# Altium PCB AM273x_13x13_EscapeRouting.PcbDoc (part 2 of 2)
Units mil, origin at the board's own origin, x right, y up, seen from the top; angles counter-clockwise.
Board outline 4950 x 3450 mil, 4 copper layers (Top Layer, GND, Power, Bottom Layer), stack 65.634 mil thick; 41 components, 133 nets, 293 pads, 159 vias.
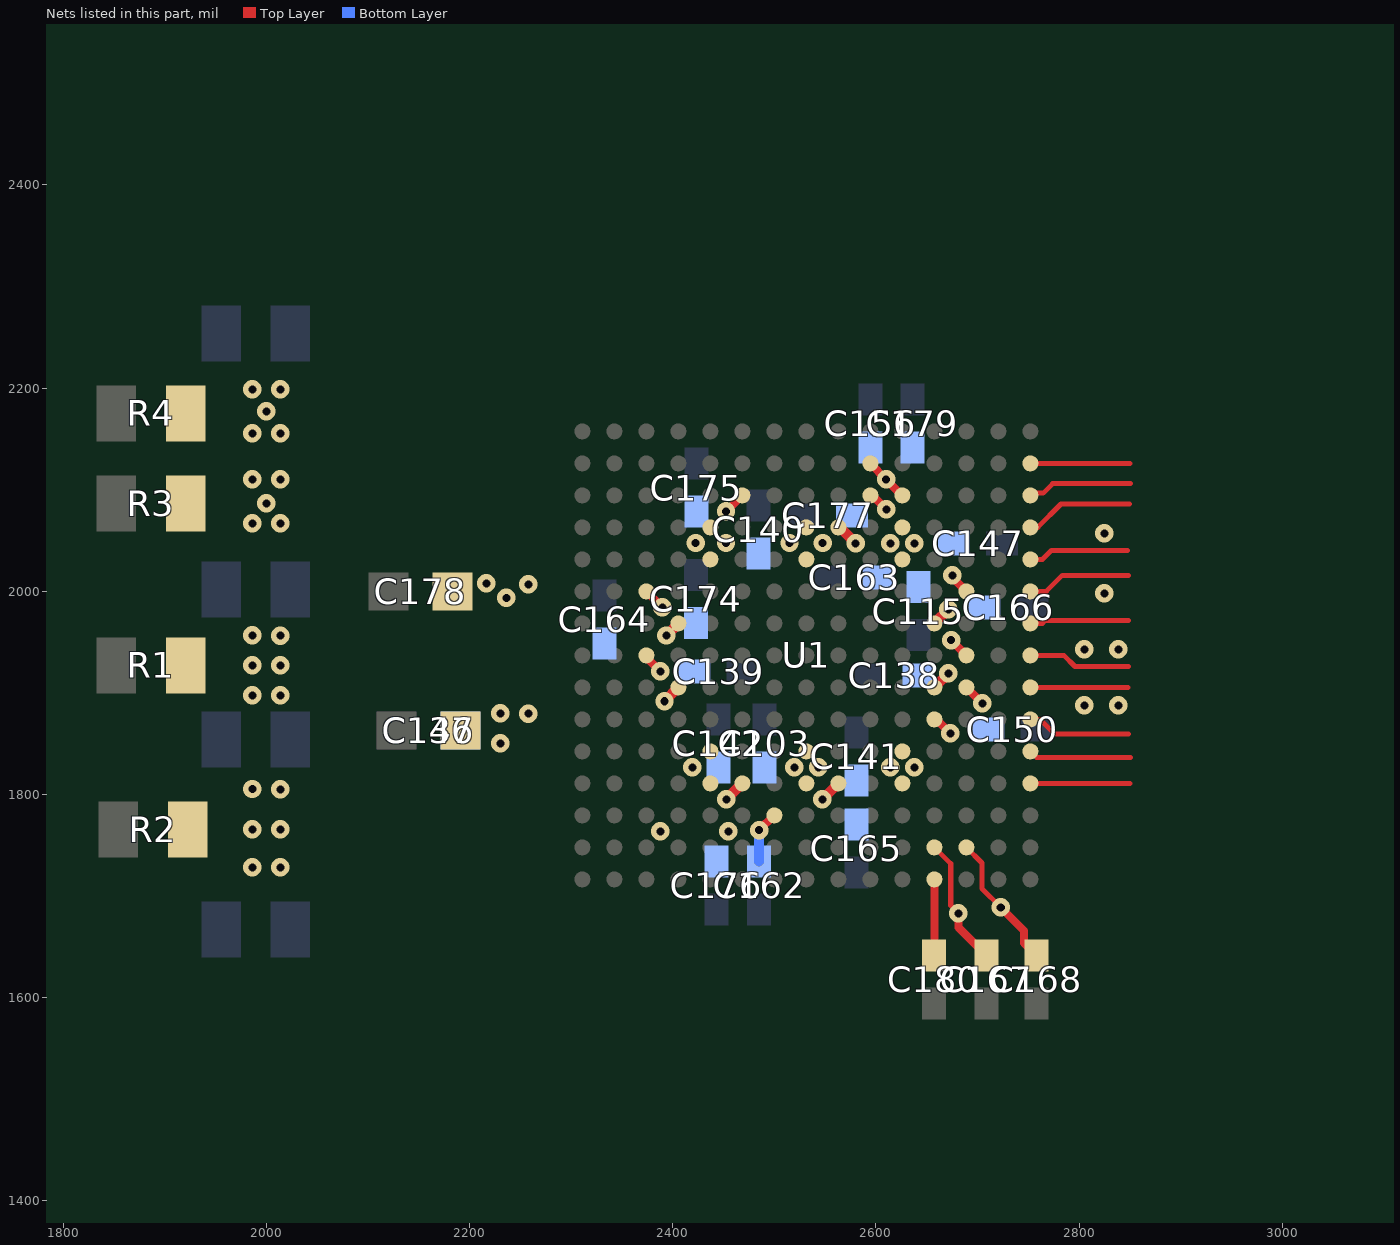
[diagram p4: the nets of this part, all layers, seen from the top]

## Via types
v1: diameter 18, hole 8, Top Layer to Bottom Layer, tented both sides, 135 vias
v2: diameter 18, hole 8, Top Layer to Bottom Layer, 24 vias

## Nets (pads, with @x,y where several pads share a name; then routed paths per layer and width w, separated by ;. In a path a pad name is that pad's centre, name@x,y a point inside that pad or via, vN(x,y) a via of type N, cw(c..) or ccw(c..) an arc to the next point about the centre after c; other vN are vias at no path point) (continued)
R4: U1.R4 | length 98
  Top Layer w5: U1.R4@2751.97,1811.02 2850,1811.02
R5: U1.R5 | length 100.9
  Top Layer w5: U1.R5@2751.97,1842.52 2757.87,1836.61 2850.39,1836.61
R6: U1.R6 | length 102.4
  Top Layer w5: U1.R6@2751.97,1874.02 2761.53,1874.02 2775.87,1859.68 2848.42,1859.68
R7: U1.R7 | length 96.2
  Top Layer w5: U1.R7@2751.97,1905.51 2848.18,1905.51
R8: U1.R8 | length 101
  Top Layer w5: U1.R8@2751.97,1937.01 2784.92,1937.01 2795.97,1925.95 2848.43,1925.95
R9: U1.R9 | length 97.6
  Top Layer w5: U1.R9@2751.97,1968.5 2763.78,1968.5 2766.59,1971.32 2848.43,1971.32
R10: U1.R10 | length 103
  Top Layer w5: U1.R10@2751.97,2000 2767.72,2000 2783.46,2015.75 2848.43,2015.75
R11: U1.R11 | length 99.1
  Top Layer w5: U1.R11@2751.97,2031.5 2763.9,2031.5 2772.76,2040.35 2847.44,2040.35
R12: U1.R12 | length 107.2
  Top Layer w5: U1.R12@2751.97,2062.99 2759.21,2062.99 2782.21,2085.98 2849.68,2085.98
R13: U1.R13 | length 104.4
  Top Layer w5: U1.R13@2751.97,2094.49 2751.97,2096.61 2764.55,2096.61 2773.92,2105.98 2850.39,2105.98
R14: U1.R14 | length 98
  Top Layer w5: U1.R14@2751.97,2125.98 2850,2125.98
VBGAP: C180.2 U1.M1 | length 75
  Top Layer w8: C180.2@2656.89,1641.73 2657.48,1642.32 U1.M1@2657.48,1716.54
VDD_1V2: C103.2 C115.2 C137.2 C138.2 C139.2 C140.2 C141.2 C142.2 C146.2 C156.2 C162.2 C179.2 R1.2 U1.D7 U1.D9 U1.E4 U1.E5 U1.E11 U1.E12 U1.G3 U1.H4 U1.H5 U1.H11 U1.H12 U1.K14 U1.L4 U1.L5 U1.L11 U1.L12 U1.L13 U1.M6 U1.M7 U1.M9 | length 196.6
  Top Layer w8: v1(2485,1765) 2499.53,1779.53 U1.G3@2500,1779.53 ; U1.K14@2594.49,2125.98 2594.49,2125.75 v1(2610,2110.24) 2625.75,2094.49 U1.L13@2625.98,2094.49 ; U1.M6@2657.48,1874.02 2659.45,1874.02 v1(2673.23,1860.24)
  Top Layer w10: v1(2391.87,1891.87) U1.D7@2405.51,1905.51 ; v1(2393.7,1956.46) 2405.51,1968.27 U1.D9@2405.51,1968.5 ; U1.M7@2657.48,1905.51 v1@2672.5,1920.49 ; U1.M9@2657.48,1968.5 v1@2672.5,1983.48
  Bottom Layer w10: C162.2@2485,1734.25 v1(2485,1765)
  other v1: 2419.29,1826.77 2519.68,1826.77 2543.31,1826.77 2614.17,1826.77 2637.8,1826.77 2230.32,1850.39 2230.32,1879.92 2257.87,1879.66 2671.26,1919.29 2671.26,1982.28 2614.17,2047.24 2637.8,2047.24 2422.5,2047.5 2452.5,2047.5 2515,2047.5 2547.5,2047.5
  other v2: 1986.22,1897.64 2013.78,1897.64 1986.22,1927.17 2013.78,1927.17 2013.78,1956.38 1986.22,1956.69
VDD_1V8: C163.2 C164.2 C165.2 C166.2 C167.2 C168.2 R2.2 U1.C8 U1.J4 U1.J12 U1.M2 U1.N2 U1.N8 | length 351.5
  Top Layer w5: U1.M2@2657.48,1748.03 2673.6,1731.91 2673.6,1690.96 2681.49,1683.07 v1(2681.1,1683.07) ; U1.N2@2688.98,1748.03 2704.39,1732.62 2704.39,1707.38 v1(2722.8,1688.98)
  Top Layer w8: U1.C8@2374.02,1937.01 2374.02,1935.04 v1(2387.8,1921.26) ; v1(2674,1951.99) U1.N8@2688.98,1937.01 ; v1(2681.1,1683.07) 2681.1,1669.29 C167.2@2708.66,1641.73 ; v1(2722.8,1688.98) 2745.86,1665.91 2745.86,1653.74 C168.2@2757.87,1641.73
  Top Layer w10: v1(2547.24,1795.27) 2547.35,1795.27 2563.1,1811.02 U1.J4@2562.99,1811.02 ; U1.J12@2562.99,2062.99 2564.25,2062.99 v1(2580,2047.24)
  other v1: 2387.8,1763.78 2454.72,1763.78 2805.12,1887.8 2838.58,1887.8 2805.12,1942.91 2838.58,1942.91
  other v2: 1986.22,1728.35 2013.78,1728.35 1986.22,1765.75 2013.78,1765.75 1986.22,1805.37 2013.78,1805.12
VDD_3V3: C147.2 C174.2 C175.2 C176.2 C177.2 C178.2 R3.2 U1.C10 U1.F4 U1.F13 U1.K13 U1.N10 | length 111.8
  Top Layer w8: U1.C10@2374.02,2000 2384.35,1989.66 v1@2389.76,1984.26 ; v1(2452.5,2078.74) 2468.25,2094.49 U1.F13@2468.5,2094.49 ; U1.K13@2594.49,2093.23 U1.K13@2594.49,2094.49 2596.45,2094.49 v1(2610.23,2080.7) ; v1(2675.2,2015.75) 2675.2,2013.78 U1.N10@2688.98,2000
  Top Layer w10: v1(2452.75,1795.25) U1.F4@2468.5,1811.02
  Bottom Layer w8: v1(2675.2,2015.75) v1@2675.2,2016.22
  other v1: 2389.76,1984.25 2236.22,1993.58 2257.87,2006.89 2216.54,2007.87
  other v2: 1986.22,2066.93 2013.78,2066.93 2000,2086.61 1986.22,2110.24 2013.78,2110.24
VPP_1P7: C150.2 R4.2 U1.N7 | length 22.3
  Top Layer w8: U1.N7@2688.98,1905.51 v1(2704.72,1889.76)
  other v1: 2824.8,1998.03 2824.8,2057.09
  other v2: 1986.22,2155.51 2013.78,2155.51 2000,2177.17 1986.22,2198.82 2013.78,2198.82
pads on no net: R1.1 R2.1 R3.1 R4.1 R5.2 R6.2 R7.2 R8.2

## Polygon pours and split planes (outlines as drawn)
VDD_1V8 on Top Layer "TOP_LAYER_VDD_1V8_P156" (solid, remove dead copper, pour order 156): 2029.53,1816.93 2029.53,1716.54 1901.57,1716.54 1901.57,1816.93
VDD_1V2 on Top Layer "TOP_LAYER_VDD_1V2_P154" (solid, remove dead copper, pour order 154): 2027.56,1968.27 2027.56,1885.12 1899.61,1885.12 1899.61,1968.27
VPP_1P7 on Top Layer "TOP_LAYER_VPP_1P7_P152" (solid, remove dead copper, pour order 152): 2027.56,2210.63 2027.56,2143.7 1899.61,2143.7 1899.61,2210.63
VDD_3V3 on Top Layer "TOP_LAYER_VDD_3V3_P150" (solid, remove dead copper, pour order 150): 2027.56,2122.05 2027.56,2055.12 1899.61,2055.12 1899.61,2122.05
GND on Top Layer "TOP_LAYER_GND_P112" (solid, remove dead copper, pour order 112): 2049.21,2030.62 2141.73,2030.62 2141.73,1969.6 2049.21,1969.6
GND on Top Layer "TOP_LAYER_GND_P110" (solid, remove dead copper, pour order 110): 2057.09,1893.7 2149.61,1893.7 2149.61,1832.68 2057.09,1832.68
VDD_1V2 on Top Layer "TOP_LAYER_VDD_1V2_P108" (solid, remove dead copper, pour order 108): 2171.26,1893.7 2171.26,1836.61 2234.25,1836.61 2277.56,1879.92 2277.56,1887.8 2271.65,1893.7
VDD_3V3 on Top Layer "TOP_LAYER_VDD_3V3_P107" (solid, remove dead copper, pour order 107): 2161.42,2019.68 2273.62,2019.68 2273.62,1978.35 2161.42,1978.35
GND on Top Layer "TOP_LAYER_GND_P030" (solid, remove dead copper, pour order 30): 2401.57,2070.87 2393.7,2062.99 2393.7,1811.02 2401.57,1803.15 2661.42,1803.15 2669.29,1811.02 2669.29,2062.99 2661.42,2070.87
VDD_1V2 on Top Layer "TOP_LAYER_VDD_1V2_P026" (solid, remove dead copper, pour order 26): 2637.8,1850.39 2645.67,1842.52 2645.67,1811.02 2637.8,1803.15 2614.17,1803.15 2606.3,1811.02 2606.3,1842.52 2614.17,1850.39
VDD_1V2 on Top Layer "TOP_LAYER_VDD_1V2_P024" (solid, remove dead copper, pour order 24): 2543.31,1850.39 2551.18,1842.52 2551.18,1811.02 2543.31,1803.15 2519.68,1803.15 2511.81,1811.02 2511.81,1842.52 2519.68,1850.39
VDD_1V2 on Top Layer "TOP_LAYER_VDD_1V2_P022" (solid, remove dead copper, pour order 22): 2448.82,1850.39 2456.69,1842.52 2456.69,1811.02 2448.82,1803.15 2425.2,1803.15 2417.32,1811.02 2417.32,1842.52 2425.2,1850.39
VDD_1V2 on Top Layer "TOP_LAYER_VDD_1V2_P020" (solid, remove dead copper, pour order 20): 2637.8,2070.87 2645.67,2062.99 2645.67,2031.5 2637.8,2023.62 2614.17,2023.62 2606.3,2031.5 2606.3,2062.99 2614.17,2070.87
VDD_1V2 on Top Layer "TOP_LAYER_VDD_1V2_P016" (solid, remove dead copper, pour order 16): 2448.82,2070.87 2456.69,2062.99 2456.69,2031.5 2448.82,2023.62 2425.2,2023.62 2417.32,2031.5 2417.32,2062.99 2425.2,2070.87
VDD_1V2 on Top Layer "TOP_LAYER_VDD_1V2_P014" (solid, remove dead copper, pour order 14): 2543.31,2070.87 2551.18,2062.99 2551.18,2031.5 2543.31,2023.62 2519.68,2023.62 2511.81,2031.5 2511.81,2062.99 2519.68,2070.87
VPP_1P7 on GND "SIGNAL_LAYER_2_VPP_1P7_P052" (solid, remove dead copper, pour order 52): 2683.07,1901.57 2683.07,1824.8 2907.48,1824.8 2907.48,2035.43 2873.08,2069.83 2811.02,2069.83 2811.02,1901.57
VDD_1V8 on GND "SIGNAL_LAYER_2_VDD_1V8_P050" (solid, pour order 50): 2669.78,1955.6 2850,1955.6 2850,1878.4 2708.21,1878.4 2652.55,1934.06
VDD_1V8 on GND "SIGNAL_LAYER_2_VDD_1V8_P048" (solid, remove dead copper, pour order 48): 2576.77,2066.93 2566.93,2057.09 2566.93,2041.34 2580.71,2027.56 2620.08,1988.19 2620.08,1966.54 2681.1,1905.51 2721.24,1905.51 2721.24,1936.24 2590.55,2066.93
VDD_1V8 on GND "SIGNAL_LAYER_2_VDD_1V8_P046" (solid, remove dead copper, pour order 46): 2391.73,1942.52 2350.62,1942.52 2318.9,1910.79 2318.9,1766.37 2352.36,1732.91 2559.06,1732.91 2572.83,1746.69 2572.83,1799.84 2562.99,1809.68 2391.73,1809.68
VDD_3V3 on GND "SIGNAL_LAYER_2_VDD_3V3_P042" (solid, remove dead copper, pour order 42): 2381.89,1992.62 2422.74,1992.62 2433.07,1982.28 2433.07,1933.93 2484.25,1882.75 2484.25,1806.12 2457.65,1779.53 2419.29,1779.53 2419.29,1814.96 2381.89,1852.36
GND on GND "SIGNAL_LAYER_2_GND_P055" (solid, remove dead copper, pour order 55): 1968.5,2519.68 3070.87,2519.68 3070.87,1417.32 1968.5,1417.32
VDD_1V2 on Power "SIGNAL_LAYER_1_VDD_1V2_P054" (solid, pour order 54): 2610.24,2122.05 2618.11,2114.17 2618.11,2106.3 2612.2,2100.39 2606.3,2100.39 2596.46,2090.55 2596.46,2064.96 2566.93,2064.96 2566.93,2090.55 2598.43,2122.05
VDD_1V8 on Power "SIGNAL_LAYER_1_VDD_1V8_P119" (solid, remove dead copper, pour order 119): 1968.5,1816.93 2420.25,1816.93 2458.66,1778.52 2458.66,1667.32 2344.49,1667.32 2295.28,1716.54 1968.5,1716.54
VDD_1V2 on Power "SIGNAL_LAYER_1_VDD_1V2_P118" (solid, remove dead copper, pour order 118): 2407.48,1823.72 2239.28,1823.72 2206.69,1856.3 2177.87,1885.12 1968.5,1885.12 1968.5,1968.5 2407.48,1968.5
VDD_3V3 on Power "SIGNAL_LAYER_1_VDD_3V3_P117" (solid, remove dead copper, pour order 117): 1968.5,2122.05 2236.22,2122.05 2275.59,2082.68 2275.59,2039.37 2289.37,2025.59 2399.61,2025.59 2399.61,1974.41 2216.54,1974.41 2192.91,1998.03 2192.91,2047.24 2185.04,2055.12 1968.5,2055.12
VPP_1P7 on Power "SIGNAL_LAYER_1_VPP_1P7_P115" (solid, remove dead copper, pour order 115): 2850.39,1962.6 2850.39,2054.9 2700.57,2204.72 1968.5,2204.72 1968.5,2149.65 2633.43,2149.65 2692.91,2090.16 2692.91,1962.6
VDD_1V8 on Power "SIGNAL_LAYER_1_VDD_1V8_P059" (solid, remove dead copper, pour order 59): 2362.2,1795.28 2362.2,1667.32 2726.38,1667.32 2850,1790.94 2850,1956.69 2749.89,1956.69 2693.9,1956.69 2693.9,1834.18 2582.16,1722.44 2507.37,1722.44 2434.54,1795.28
VDD_3V3 on Power "SIGNAL_LAYER_1_VDD_3V3_P058" (solid, remove dead copper, pour order 58): 2460.63,2068.9 2610,2068.9 2610,2147.64 2460.63,2147.64
VDD_3V3 on Power "SIGNAL_LAYER_1_VDD_3V3_P040" (solid, remove dead copper, pour order 40): 2470.47,2076.77 2462.6,2068.9 2401.57,2068.9 2395.67,2062.99 2395.67,2007.4 2390.23,2001.97 2336.61,2001.97 2318.9,2019.68 2318.9,2110.36 2356.17,2147.64 2470.47,2147.64
VDD_3V3 on Power "SIGNAL_LAYER_1_VDD_3V3_P034" (solid, remove dead copper, pour order 34): 2677.17,1998.03 2694.88,2015.75 2694.88,2096.23 2643.48,2147.64 2604.33,2147.64 2604.33,2076.33 2622.49,2076.33 2651.57,2047.24 2651.57,2013.78 2667.32,1998.03
VDD_1V2 on Power "SIGNAL_LAYER_1_VDD_1V2_P056" (solid, remove dead copper, pour order 56): 2401.57,2070.87 2378.94,2048.23 2378.94,1825.79 2470.47,1734.25 2592.52,1734.25 2688.98,1830.71 2688.98,1996.06 2614.17,2070.87
GND on Bottom Layer "BOTTOM_LAYER_GND_P162" (solid, remove dead copper, pour order 162): 2003.94,1694.88 2096.46,1694.88 2096.46,1639.76 2003.94,1639.76
GND on Bottom Layer "BOTTOM_LAYER_GND_P160" (solid, remove dead copper, pour order 160): 2003.94,2281.5 2096.46,2281.5 2096.46,2226.38 2003.94,2226.38
GND on Bottom Layer "BOTTOM_LAYER_GND_P158" (solid, remove dead copper, pour order 158): 2003.94,2029.53 2096.46,2029.53 2096.46,1974.41 2003.94,1974.41
GND on Bottom Layer "BOTTOM_LAYER_GND_P116" (solid, remove dead copper, pour order 116): 2775.59,1883.3 2940.94,1883.3 2940.94,1836.61 2775.59,1836.61
GND on Bottom Layer "BOTTOM_LAYER_GND_P114" (solid, remove dead copper, pour order 114): 2567.72,2181.1 2671.26,2181.1 2671.26,2236.22 2645.67,2261.81 2594.49,2261.81 2567.92,2235.25
VDD_1V2 on Bottom Layer "BOTTOM_LAYER_VDD_1V2_P113" (solid, pour order 113): 2582.68,2157.48 2647.64,2157.48 2647.64,2103.35 2582.68,2103.35
GND on Bottom Layer "BOTTOM_LAYER_GND_P111" (solid, remove dead copper, pour order 111): 2003.94,1892.83 2149.61,1892.83 2149.61,1826.54 2003.94,1826.54
VDD_1V2 on Bottom Layer "BOTTOM_LAYER_VDD_1V2_P109" (solid, remove dead copper, pour order 109): 2171.26,1893.7 2171.26,1836.61 2234.25,1836.61 2277.56,1879.92 2277.56,1887.8 2271.65,1893.7
GND on Bottom Layer "BOTTOM_LAYER_GND_P106" (solid, remove dead copper, pour order 106): 2273.62,2194.88 2789.37,2194.88 2789.37,1679.13 2273.62,1679.13
VDD_1V8 on Bottom Layer "BOTTOM_LAYER_VDD_1V8_P105" (solid, remove dead copper, pour order 105): 2541.34,1803.15 2541.34,1753.94 2594.49,1753.94 2594.49,1803.15
VDD_1V2 on Bottom Layer "BOTTOM_LAYER_VDD_1V2_P104" (solid, pour order 104): 2387.8,1964.57 2387.8,1887.8 2404.92,1887.8 2425.2,1908.07 2425.2,1964.57
VDD_3V3 on Bottom Layer "BOTTOM_LAYER_VDD_3V3_P103" (solid, remove dead copper, pour order 103): 2435.04,1952.76 2435.04,1986.22 2401.14,2020.12 2384.57,2020.12 2379.92,2015.47 2379.92,1952.76
VDD_1V8 on Bottom Layer "BOTTOM_LAYER_VDD_1V8_P102" (solid, remove dead copper, pour order 102): 2320.87,1974.41 2395.67,1974.41 2395.67,1915.03 2320.87,1915.03
VDD_1V2 on Bottom Layer "BOTTOM_LAYER_VDD_1V2_P101" (solid, remove dead copper, pour order 101): 2415.35,2068.9 2543.31,2068.9 2557.09,2055.12 2557.09,2039.37 2537.4,2019.68 2415.35,2019.68
VDD_3V3 on Bottom Layer "BOTTOM_LAYER_VDD_3V3_P100" (solid, remove dead copper, pour order 100): 2409.45,2102.36 2462.6,2102.36 2462.6,2076.77 2454.72,2068.9 2409.45,2068.9
VDD_1V2 on Bottom Layer "BOTTOM_LAYER_VDD_1V2_P099" (solid, remove dead copper, pour order 99): 2604.33,2061.02 2604.33,1968.5 2685.04,1968.5 2685.04,2061.02
VDD_1V8 on Bottom Layer "BOTTOM_LAYER_VDD_1V8_P067" (solid, remove dead copper, pour order 67): 2614.17,2001.97 2614.17,2026.58 2580.32,2060.43 2574.54,2060.43 2565.55,2051.45 2565.55,2025 2588.58,2001.97
VDD_3V3 on Bottom Layer "BOTTOM_LAYER_VDD_3V3_P066" (solid, remove dead copper, pour order 66): 2555.12,2092.52 2643.7,2092.52 2669.29,2066.93 2696.85,2066.93 2696.85,2021.65 2681.1,2005.91 2673.23,2005.91 2651.57,2027.56 2651.57,2053.15 2641.73,2062.99 2555.12,2062.99
VDD_1V8 on Bottom Layer "BOTTOM_LAYER_VDD_1V8_P065" (solid, remove dead copper, pour order 65): 2726.38,1998.03 2726.38,1962.6 2700.79,1937.01 2659.45,1937.01 2659.45,1998.03
VDD_3V3 on Bottom Layer "BOTTOM_LAYER_VDD_3V3_P064" (solid, remove dead copper, pour order 64): 2665.35,2061.02 2665.35,2013.78 2673.23,2005.91 2681.1,2005.91 2696.85,2021.65 2696.85,2061.02
VPP_1P7 on Bottom Layer "BOTTOM_LAYER_VPP_1P7_P063" (solid, remove dead copper, pour order 63): 2690.94,1846.46 2690.94,1903.54 2730.32,1903.54 2730.32,1846.46
VDD_1V2 on Bottom Layer "BOTTOM_LAYER_VDD_1V2_P062" (solid, remove dead copper, pour order 62): 2625.98,1935.04 2673.23,1935.04 2685.04,1923.23 2685.04,1899.61 2625.98,1899.61
VDD_1V2 on Bottom Layer "BOTTOM_LAYER_VDD_1V2_P061" (solid, remove dead copper, pour order 61): 2411.42,1840.55 2421.26,1850.39 2639.76,1850.39 2649.61,1840.55 2649.61,1812.99 2639.76,1803.15 2421.26,1803.15 2411.42,1812.99
VDD_3V3 on Bottom Layer "BOTTOM_LAYER_VDD_3V3_P060" (solid, pour order 60): 2429.13,1718.5 2461.51,1718.5 2461.51,1803.15 2429.13,1803.15

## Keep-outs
Keep-Out Layer:
  text ".Layer_Name" at 577,-858.49 h60

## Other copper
Top Layer:
  text ".Layer_Name" at 577,-858.49 h60
Bottom Layer:
  text ".Layer_Name" at 577,-858.49 h60

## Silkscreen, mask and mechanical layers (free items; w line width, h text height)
Top Overlay:
  text "VPP" at 1964.57,2157.48 h40
  text "VDD_3V3" at 1962.6,2066.93 h40
  text "VDD_1V2" at 1962.6,1907.48 h40
  text "VDD_1V8" at 1962.6,1746.06 h40
  text "'.PRJ_Number'.PCB_Rev" at 1845,125.77 h108.27
  text ".Layer_Name" at 577,-858.49 h60
Bottom Overlay:
  text ".Layer_Name" at 577,-858.49 h60
Top Paste:
  text ".Layer_Name" at 577,-858.49 h60
Bottom Paste:
  text ".Layer_Name" at 577,-858.49 h60
Top Solder:
  text ".Layer_Name" at 577,-858.49 h60
  text ".Layer_Name" at 577,-858.49 h60
Bottom Solder:
  text ".Layer_Name" at 577,-858.49 h60
Drill Guide:
  text ".Layer_Name" at 577,-858.49 h60
M1 Board Outline:
  the board outline again, w10
  text ".Layer_Name" at 577,-858.49 h60
M2 Board Dimensions:
  rectangle: 0,-275 125,-150
  rectangle: 125,-400 500,-275
  lines w7: 0,-275 1000,-275 ; 125,-400 125,-150 ; 250,-400 250,-150 ; 500,-400 500,-150 ; 750,-400 750,-150 ; 0,-400 1000,-400 1000,-150 0,-150 0,-400
  text ".Layer_Name" at 577,-858.49 h60
M3 3D STEP Top:
  text ".Layer_Name" at 577,-858.49 h60
M4 3D STEP Bottom:
  text ".Layer_Name" at 577,-858.49 h60
M5 Assembly Top:
  lines w10: -292,-930.17 6308,-930.17 ; -292,-726.83 6310,-726.83 ; -292,-523.5 -292,-1133.5 3713,-1133.5 6310,-1133.5 6310,-523.5 -291.5,-523.5 -291.5,-1133.5 1284,-1133.5 ; 2173,-1133.5 2173,-523.5 ; 3440,-726.83 3440,-523.5 ; 4280,-726.83 4280,-523.5 ; 4902,-1140 4902,-937.17
  text "COMPONENTS MARKED 'DNP' SHOULD NOT BE POPULATED." at 1153.5,-318.5 h60
  text "ASSEMBLY VARIANT:" at 1153,-434 h60
  text ".VariantName" at 2189,-434 h60
  text "PCB VIEWED FROM TOP SIDE" at -228.5,-655.67 h60
  text "BOARD #:" at 2248,-655.67 h60
  text ".PRJ_Number" at 2793.5,-655.67 h60
  text "REV:" at 3638,-655.67 h60
  text ".PCB_Rev" at 3929.5,-655.67 h60
  text "SVN REV:" at 4476,-655.67 h60
  text ".VersionControl_RevNumber" at 4982,-655.67 h60
  text "TID #:" at 2248,-859 h60
  text ".TID" at 2793.5,-859 h60
  text "PLOT NAME =" at -228.5,-1064.34 h60
  text ".plot_File_Name" at 577,-1064.34 h60
  text "GENERATED    :" at 2250,-1064.34 h60
  text ".Print_Date" at 3119.5,-1064.34 h60
  text ".Print_Time" at 3848.5,-1064.34 h60
  text "TEXAS INSTRUMENTS" at 5113,-1064.34 h60
M6 Assembly Bottom:
  lines w10: -292.5,-727.33 6309.5,-727.33 ; -290.5,-930.67 6309.5,-930.67 ; 1115.5,-1140.5 1115.5,-937.67 ; 1737.5,-727.33 1737.5,-524 ; 2577.5,-727.33 2577.5,-524 ; 3844.5,-1134 3844.5,-524 ; 4733.5,-1134 6309,-1134 6309,-524 -292.5,-524 -292.5,-1134 2304.5,-1134 6309.5,-1134 6309.5,-524
  text "COMPONENTS MARKED 'DNP' SHOULD NOT BE POPULATED." at 6102,-318 h60
  text ".VariantName" at 5058,-434 h60
  text "ASSEMBLY VARIANT:" at 6097,-434 h60
  text ".VersionControl_RevNumber" at 1035.5,-656.17 h60
  text "SVN REV:" at 1541.5,-656.17 h60
  text ".PCB_Rev" at 2088,-656.17 h60
  text "REV:" at 2379.5,-656.17 h60
  text ".PRJ_Number" at 3224,-656.17 h60
  text "BOARD #:" at 3769.5,-656.17 h60
  text "PCB VIEWED FROM BOTTOM SIDE" at 6246,-656.17 h60
  text ".TID" at 3224,-859.5 h60
  text "TID #:" at 3769.5,-859.5 h60
  text "TEXAS INSTRUMENTS" at 904.5,-1064.84 h60
  text ".Print_Time" at 2169,-1064.84 h60
  text ".Print_Date" at 2898,-1064.84 h60
  text "GENERATED    :" at 3767.5,-1064.84 h60
  text ".plot_File_Name" at 5440.5,-1064.84 h60
  text "PLOT NAME =" at 6246,-1064.84 h60
M9 Title Sheet:
  drawing of 57 lines, arcs and shapes, not listed
  text "1" at 739.84,8036.5 h70
  text "2" at 3235.5,8036.5 h70
  text "3" at 5724.84,8036.5 h70
  text "4" at 8231.51,8036.5 h70
  text "5" at 10730.5,8036.5 h70
  text "6" at 13235.5,8036.5 h70
  text "A" at -416.5,6893.5 h70
  text "A" at 14383.5,6893.5 h70
  text "B" at -416.5,4513.5 h70
  text "B" at 14383.5,4513.5 h70
  text "C" at -416.5,2138.5 h70
  text "C" at 14383.5,2138.5 h70
  text "PROJECT TITLE:" at 11343.5,277.5 h45
  text ".PRJ_Title" at 11393.5,144.17 h70
  text "DESIGNED FOR:" at 11343.5,-23.5 h45
  text ".PRJ_Customer" at 11393.5,-163.5 h70
  text "D" at -416.5,-231.5 h70
  text "D" at 14383.5,-231.5 h70
  text "FILE NAME:" at 11343.5,-323.5 h45
  text ".PCB_File_Name_No_Path" at 11393.5,-443.5 h70
  text "Texas Instruments (TI) and/or its licensors do not warrant the accuracy or completeness of this specification" at 6374,-605.34 h45
  text "ENGINEER:" at 11343.5,-613.5 h45
  text "LAYOUT BY:" at 12848.5,-613.5 h45
  text "or any information contained therein. TI and/or its licensors do not warrant that this design will meet" at 6329.01,-718 h45
  text ".PRJ_Engineer" at 11393.5,-768.49 h70
  text ".PCB_Layout" at 12899,-768.49 h70
  text "the specifications, will be suitable for your application or fit for any particular purpose, or will operate in" at 6329.01,-830.67 h45
  text ".Layer_Name" at 577,-858.49 h60
  text "ALTIUM DESIGNER VERSION:" at 12848.5,-923.5 h45
  text "an implementation. TI and/or its licensors do not warrant that the design is production worthy. You should" at 6329.01,-943.33 h45
  text "completely validate and test your design implementation to confirm the system functionality for your application." at 6374,-1056 h45
  text ".print_Scale" at 11393.5,-1056.83 h70
  text ".Application_BuildNumber" at 12899,-1056.83 h70
  text "1" at 739.84,-1263.5 h70
  text "2" at 3235.5,-1263.5 h70
  text "3" at 5724.84,-1263.5 h70
  text "4" at 8231.51,-1263.5 h70
  text "5" at 10730.5,-1263.5 h70
  text "6" at 13235.5,-1263.5 h70
M10 Fab Notes:
  drawing of 189 lines, arcs and shapes, not listed
  text "DESIGN INFORMATION" at 12382.02,6356.17 h60
  text "MIN. TRACK WIDTH:" at 11737.46,6224.05 h60
  text "4" at 12833.7,6224.05 h60
  text "MIL" at 12988.46,6224.05 h60
  text "4" at 12832.68,6102.36 h60
  text "MIN. CLEARANCE:" at 11737.46,6099.92 h60
  text "MIL" at 12988.46,6099.92 h60
  text "MIN. VIA PAD SIZE:" at 11737.46,5975.8 h60
  text "18" at 12803.71,5975.8 h60
  text "MIL" at 12988.46,5975.8 h60
  text "0.05mm (2MIL)" at 12432.46,5845.9 h60
  text "MINIMUM ANNULAR RING" at 11408.23,5837.67 h60
  text "EXTERNAL" at 13140.46,5837.67 h60
  text "PER" at 11608.23,5727.55 h60
  text "IPC-D-275 CLASS 2 LEVEL C" at 11828.23,5727.54 h60
  text "MIL, HOLES" at 13316.46,5627.07 h60
  text "+/-" at 12924,5618.48 h60
  text "+/-" at 13778,5618.48 h60
  text "REGISTRATION TOLERANCES:" at 11408.23,5617.42 h60
  text "METAL" at 12608,5617.42 h60
  text "5" at 13184.2,5617.42 h60
  text "3" at 14017.2,5617.42 h60
  text "MIL" at 14133.46,5617.42 h60
  text "HOLE SIZE TOLERANCE (UNLESS OTHERWISE SPECIFIED):" at 11408.23,5519.1 h60
  text "+/-" at 13778,5516.23 h60
  text "3" at 14017.2,5515.17 h60
  text "MIL" at 14133.46,5515.17 h60
  text "MATERIAL:" at 11333.46,5377.52 h60
  text "FR-4 High Tg" at 12319.9,5249 h60
  text "X" at 12175.46,5241.01 h60
  text "FR-408" at 11754.46,5236.49 h60
  text "OTHER" at 13242.46,5236.49 h60
  text "62 MIL (1.6mm) +/-10%" at 12074.56,5093.46 h60
  text "X" at 11954.46,5091.01 h60
  text "THICKNESS:" at 11408.23,5085.24 h60
  text "OTHER" at 13359.46,5085.24 h60
  text "TOLERANCE:" at 11408.23,4946.92 h60
  text "X" at 12256.46,4946.92 h60
  text "ANSI IPC-6012 TYPE 3 CLASS 2" at 12434.48,4946.92 h60
  text "OTHER +/-" at 12434.46,4802.73 h60
  text "BOW & TWIST:" at 11408.23,4657.54 h60
  text "X" at 12256.46,4657.54 h60
  text "ANSI IPC-6012 TYPE 3 CLASS 2" at 12434.48,4657.54 h60
  text "OTHER +/-" at 12434.46,4510.85 h60
  text "DRILLING:" at 11333.46,4380.23 h60
  text "NC_DRILL FILES" at 13094.46,4275.04 h60
  text "REFERENCE:" at 11408.23,4271.1 h60
  text "X" at 12065.46,4271.01 h60
  text "AS SHOWN" at 12243.46,4271.1 h60
  text "X" at 12966.46,4271.1 h60
  text "OTHER" at 13392.46,4128.85 h60
  text "PTH COPPER THICKNESS:" at 11407.91,4125.32 h60
  text "X" at 12547.14,4125.32 h60
  text "20-30 um" at 12675.14,4125.32 h60
  text "BOARD FINISH:" at 11333.46,3977.73 h60
  text "SILKSCREEN:" at 11488.68,3867.6 h60
  text "X" at 12446.46,3867.6 h60
  text "TOP" at 12563.46,3867.6 h60
  text "X" at 12956.46,3867.6 h60
  text "BOTTOM" at 13074.46,3867.6 h60
  text "SILKSCREEN COLOR:" at 11488.68,3712.41 h60
  text "X" at 12445.46,3712.41 h60
  text "WHITE" at 12563.46,3712.41 h60
  text "OTHER" at 13074.46,3712.41 h60
  text "X" at 12576.46,3568.96 h60
  text "GREEN" at 12694.46,3568.96 h60
  text "OTHER" at 13312.46,3568.96 h60
  text "SOLDER RESIST COLOR:" at 11488.68,3562.1 h60
  text "X" at 12576.46,3414.71 h60
  text "MATTE" at 12694.46,3414.71 h60
  text "SEMI-GLOSS" at 13312,3414.07 h60
  text "IMMERSION GOLD (ENIG)" at 12394.46,3241.94 h60
  text "ENEPIG" at 13732,3234.72 h60
  text "SURFACE FINISH:" at 11333.46,3233.72 h60
  text "X" at 12216.46,3233.72 h60
  text "IMM. TIN/SILVER OR EQUIV" at 11663,3096.4 h60
  text "OTHER" at 13094.46,3092.47 h60
  text "ARRAY/PANEL:" at 11333.46,2937.09 h60
  text "CUT AND TRIM PER M1 BOARD OUTLINE" at 12394.46,2928.87 h60
  text "N.C. ROUTE" at 12394.46,2792.9 h60
  text "X" at 13082.46,2792.9 h60
  text "V. SCORE" at 13260.46,2792.9 h60
  text "CERTIFICATION:" at 11333.46,2663.77 h60
  text "MATERIALS AND WORKMANSHIP FOR ALL PCBS" at 12058.46,2663.77 h60
  text "TO MEET OR EXCEED THE REQUIREMENTS OF:" at 12058.46,2569.71 h60
  text "X" at 11695.97,2441.08 h60
  text "ANSI IPC-A-600F CLASS ->" at 11823.96,2441.08 h60
  text "X" at 13471.97,2441.08 h60
  text "2" at 13581.96,2441.08 h60
  text "1" at 13266.96,2439.58 h60
  text "3" at 13935.96,2439.58 h60
  text "X" at 12507.97,2293.39 h60
  text "RoHS" at 12635.96,2293.39 h60
  text "OTHER" at 13280.36,2293.39 h60
  text "PER ORDER" at 13677.42,2293.39 h60
  text "ALL BOARDS MUST MEET OR EXCEED UL94-V0 REQUIREMENTS." at 11361,2139.57 h60
  text "PCB MUST BEAR THE UL94V-0 UL REGISTERED MATERIAL ID NUMBER" at 11361,2023.5 h60
  text "ADDITIONAL REQUIREMENTS:" at 11333.46,1854.08 h60
  text "MICROSECTION:" at 11408.23,1746.95 h60
  text "YES" at 12313.96,1746.95 h60
  text "REQUIRED" at 13175.46,1602.62 h60
  text "BARE BOARD ELEC. TEST:" at 11408.23,1599.76 h60
  text "NONE" at 12713.96,1599.76 h60
  text "X" at 13057.46,1599.76 h60
  text "PER ORDER" at 13767.46,1599.76 h60
  text "XX MIL VIAS REQUIRE NON-CONDUCTIVE FILL AND PLANARIZE" at 11576.38,1394.82 h59
  text "XX MIL VIAS REQUIRE CONDUCTIVE FILL AND PLANARIZE" at 11584.38,1290.84 h60
  text "OUTER XX MIL TRACES REQUIRE 50 OHM SINGLE-ENDED IMPEDANCE" at 11583.39,1127.46 h58
  text "LAYER 2 & 3 (INNER LAYERS) XX MIL WIDE, XX MIL SPACE / TRACES REQUIRE 100 OHM DIFFERENTIAL IMPEDANCE" at 11575.39,891.74 h60
  text ".Layer_Name" at 577,-858.49 h60
M11 Gerber Information:
  lines w10: -292,-930.17 6308,-930.17 ; -292,-726.83 6310,-726.83 ; -292,-523.5 -292,-1133.5 3713,-1133.5 6310,-1133.5 6310,-523.5 -291.5,-523.5 -291.5,-1133.5 1284,-1133.5 ; 2173,-1133.5 2173,-523.5 ; 3440,-726.83 3440,-523.5 ; 4280,-726.83 4280,-523.5 ; 4902,-1140 4902,-937.17
  text "ALL ARTWORK VIEWED FROM TOP SIDE" at -228.5,-655.67 h60
  text "BOARD #:" at 2248,-655.67 h60
  text ".PRJ_Number" at 2793.5,-655.67 h60
  text "REV:" at 3638,-655.67 h60
  text ".PCB_Rev" at 3929.5,-655.67 h60
  text "SVN REV:" at 4476,-655.67 h60
  text ".VersionControl_RevNumber" at 4982,-655.67 h60
  text "LAYER NAME =" at -228.5,-858.49 h60
  text "TID #:" at 2248,-859 h60
  text ".TID" at 2793.5,-859 h60
  text "PLOT NAME =" at -228.5,-1064.34 h60
  text ".plot_File_Name" at 577,-1064.34 h60
  text "GENERATED    :" at 2250,-1064.34 h60
  text ".Print_Date" at 3119.5,-1064.34 h60
  text ".Print_Time" at 3848.5,-1064.34 h60
  text "TEXAS INSTRUMENTS" at 5113,-1064.34 h60
M12 Stackup:
  drawing of 295 lines, arcs and shapes, not listed
  text "Layer" at 9821.59,7694.94 h60
  text "Name" at 10231.51,7694.94 h60
  text "Material" at 11161.25,7694.94 h60
  text "Thickness" at 12021.02,7694.94 h60
  text "Constant" at 12670.85,7694.94 h60
  text "Board Layer Stack" at 13240.71,7694.94 h60
  text "Top Overlay" at 10231.51,7574.94 h60
  text "Top Solder" at 10231.51,7454.94 h60
  text "Solder Resist" at 11161.25,7454.94 h60
  text "0.40mil" at 12021.02,7454.94 h60
  text "3.5" at 12670.85,7454.94 h60
  text "1" at 9821.59,7334.94 h60
  text "Top Layer" at 10231.51,7334.94 h60
  text "1.40mil" at 12021.02,7334.94 h60
  text "Dielectric 2" at 10231.51,7214.94 h60
  text "370HR" at 11161.25,7214.94 h60
  text "10.00mil" at 12021.02,7214.94 h60
  text "4.2" at 12670.85,7214.94 h60
  text "2" at 9821.59,7094.94 h60
  text "GND" at 10231.51,7094.94 h60
  text "1.42mil" at 12021.02,7094.94 h60
  text "Dielectric1" at 10231.51,6974.94 h60
  text "FR-4 High Tg" at 11161.25,6974.94 h60
  text "40.00mil" at 12021.02,6974.94 h60
  text "4.2" at 12670.85,6974.94 h60
  text "3" at 9821.59,6854.94 h60
  text "Power" at 10231.51,6854.94 h60
  text "1.42mil" at 12021.02,6854.94 h60
  text "Dielectric 3" at 10231.51,6734.94 h60
  text "370HR" at 11161.25,6734.94 h60
  text "10.00mil" at 12021.02,6734.94 h60
  text "4.2" at 12670.85,6734.94 h60
  text "4" at 9821.59,6614.94 h60
  text "Bottom Layer" at 10231.51,6614.94 h60
  text "1.40mil" at 12021.02,6614.94 h60
  text "Bottom Solder" at 10231.51,6494.94 h60
  text "Solder Resist" at 11161.25,6494.94 h60
  text "0.40mil" at 12021.02,6494.94 h60
  text "3.5" at 12670.85,6494.94 h60
  text "Bottom Overlay" at 10231.51,6374.94 h60
  text ".Layer_Name" at 577,-858.49 h60
M13 Component Bodies Top:
  text ".Layer_Name" at 577,-858.49 h60
M14 Component Bodies Bottom:
  text ".Layer_Name" at 577,-858.49 h60
M15 Courtyards Top:
  text ".Layer_Name" at 577,-858.49 h60
M16 Courtyards Bottom:
  text ".Layer_Name" at 577,-858.49 h60
Drill Drawing:
  lines w10: 5335.98,3311.15 5391.1,3311.15 5391.1,3366.28 5335.98,3366.28 5335.98,3311.15
  lines w12: 5286,3273.95 8512.8,3273.95 ; 5286,3397.97 8512.8,3397.97 ; 5623.36,3149.92 5623.36,3522 ; 5955.06,3149.92 5955.06,3522 ; 6590.91,3149.92 6590.91,3522 ; 6849.71,3149.92 6849.71,3522 ; 7224.46,3149.92 7224.46,3522 ; 7947,3149.92 7947,3522 ; 5286,3149.92 8512.8,3149.92 8512.8,3522 5286,3522 5286,3149.92
  text "Symbol" at 5360.42,3435.18 h72
  text "Quantity" at 5660.57,3435.18 h72
  text "Finished Hole Size" at 5992.26,3435.18 h72
  text "Plated" at 6628.12,3435.18 h72
  text "Hole Type" at 6886.92,3435.18 h72
  text "Drill Layer Pair" at 7261.67,3435.18 h72
  text "Hole Tolerance" at 7984.21,3435.18 h72
  text "159" at 5660.57,3311.15 h60
  text "8.00mil (0.203mm)" at 5992.26,3311.15 h60
  text "PTH" at 6628.12,3311.15 h60
  text "Round" at 6886.92,3311.15 h60
  text "Top Layer - Bottom Layer" at 7261.67,3311.15 h60
  text "159 Total" at 5660.57,3187.13 h60
  text ".Layer_Name" at 577,-858.49 h60
M17 Embedded Cavity:
  text ".Layer_Name" at 577,-858.49 h60
M18 Embedded Assembly:
  text ".Layer_Name" at 577,-858.49 h60
M19 Embedded Keepout:
  text ".Layer_Name" at 577,-858.49 h60

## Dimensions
0,-400 to 1000,-400 on M2 Board Dimensions
0,0 to 0,3450 on M2 Board Dimensions
0,0 to 4950,0 on M2 Board Dimensions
